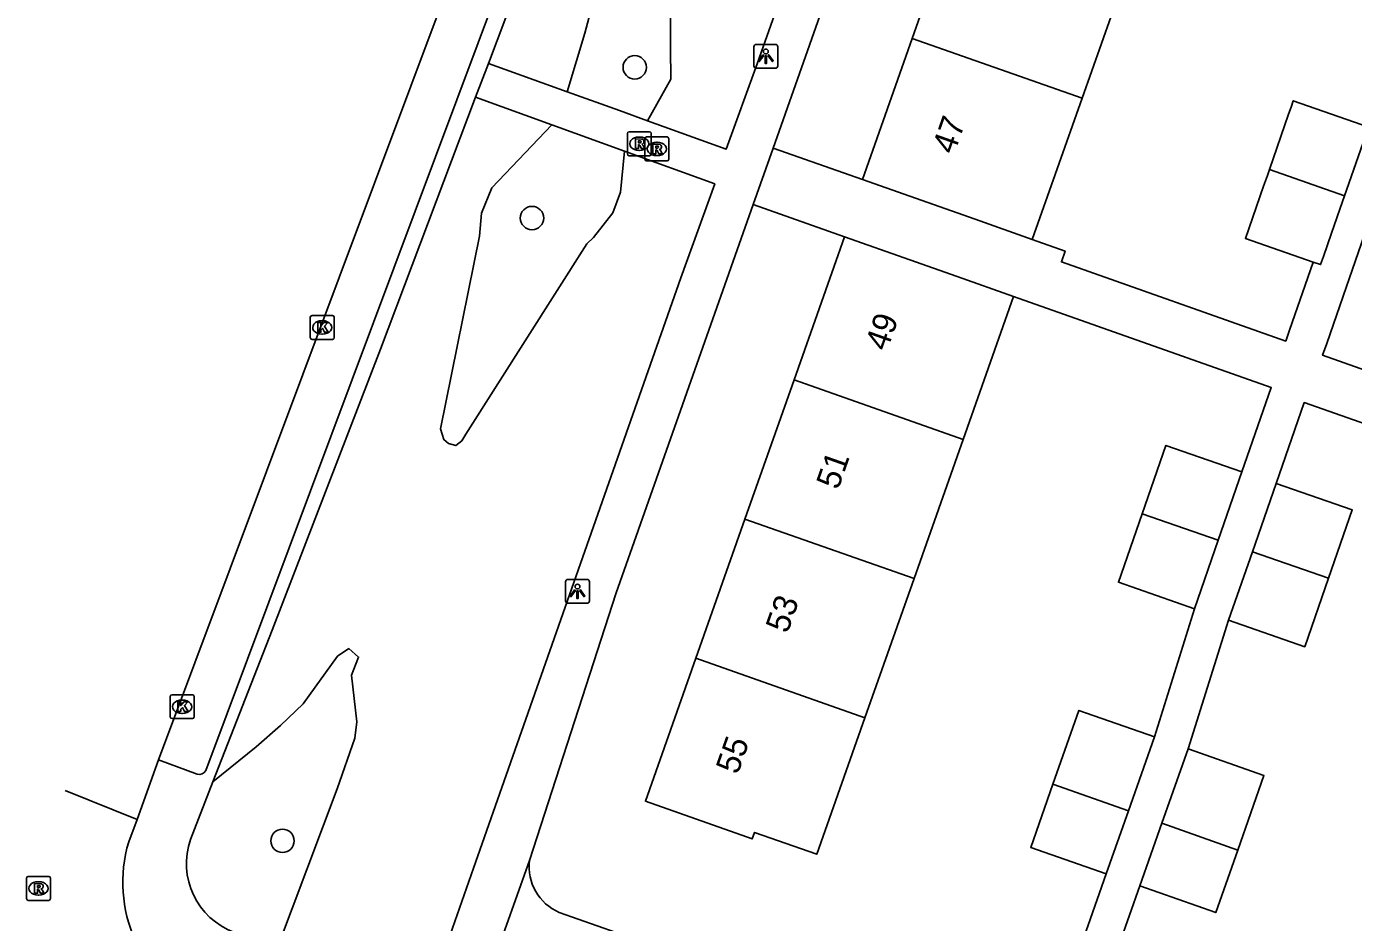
# Model space of a CAD drawing. Extents: x 163268 to 164360, y 381529 to 382285.
# Drawn here: x 163695 to 163750.6, y 381885.6 to 381923.1 of the extents above; entities that cross this region are included whole.
import ezdxf

# ---------------------------------------------------------------- set-up
doc = ezdxf.new("R2010")
doc.units = 0
for name, color, linetype in [('IMGEO_Boom', 7, 'Continuous'), ('IMGEO_Groenvoorziening', 7, 'Continuous'), ('IMGEO_Kolk', 7, 'Continuous'), ('IMGEO_Lichtpunt', 7, 'Continuous'), ('IMGEO_Pand', 7, 'Continuous'), ('IMGEO_Pand_nummerreeks', 7, 'Continuous'), ('IMGEO_Rijbaan_lokaal_open', 7, 'Continuous'), ('IMGEO_Rioolput', 7, 'Continuous'), ('IMGEO_Voetpad_open', 7, 'Continuous')]:
    doc.layers.add(name, color=color, linetype=linetype)

msp = doc.modelspace()

# ---------------------------------------------------------------- linework, layer by layer
at = {"layer": 'IMGEO_Boom'}
for centre in [(163720.477, 381921.428), (163716.178, 381915.121), (163705.736, 381889.056)]:
    msp.add_circle(centre, 0.489, dxfattribs=at)
at = {"layer": 'IMGEO_Groenvoorziening'}
for points in [[(163721.009, 381919.193), (163721.993, 381920.936), (163721.972, 381922.226), (163721.972, 381924.662), (163722.944, 381927.485), (163722.638, 381928.208), (163722.11, 381928.987), (163721.665, 381929.598), (163721.554, 381930.433), (163721.693, 381930.683), (163722.027, 381931.35), (163722.527, 381933.158), (163722.416, 381933.964), (163722.075, 381934.429), (163720.785, 381934.47), (163720.171, 381933.938), (163719.659, 381932.422), (163719.331, 381930.907), (163718.942, 381929.249), (163719.249, 381927.693), (163719.188, 381926.444), (163718.881, 381924.703), (163718.389, 381922.861), (163717.645, 381920.405)], [(163717.015, 381919.02), (163714.499, 381916.391), (163714.069, 381915.326), (163713.987, 381914.363), (163712.349, 381906.295), (163712.488, 381905.85), (163712.683, 381905.683), (163712.989, 381905.599), (163713.239, 381905.794), (163713.406, 381906.072), (163718.48, 381914.04), (163718.758, 381914.302), (163719.556, 381915.346), (163719.884, 381916.206), (163720.049, 381917.918)], [(163705.53, 381884.589), (163708.029, 381891.227), (163708.766, 381893.356), (163708.844, 381894.037), (163708.627, 381895.991), (163708.924, 381896.746), (163708.513, 381897.1), (163708.033, 381896.78), (163706.596, 381894.789), (163705.654, 381893.889), (163704.63, 381892.988), (163702.826, 381891.528)]]:
    msp.add_lwpolyline(points, dxfattribs=at)
at = {"layer": 'IMGEO_Kolk'}
for p, q in [((163706.901, 381910.117), (163706.901, 381910.969)), ((163706.976, 381911.043), (163707.828, 381911.043)), ((163707.389, 381910.823), (163707.414, 381910.823)), ((163707.902, 381910.969), (163707.902, 381910.117)), ((163707.828, 381910.043), (163706.976, 381910.043)), ((163707.412, 381910.263), (163707.387, 381910.263)), ((163701.038, 381894.244), (163701.038, 381895.096)), ((163701.113, 381895.17), (163701.965, 381895.17)), ((163702.039, 381895.096), (163702.039, 381894.244)), ((163701.526, 381894.95), (163701.551, 381894.95)), ((163701.965, 381894.17), (163701.113, 381894.17)), ((163701.549, 381894.39), (163701.524, 381894.39))]:
    msp.add_line(p, q, dxfattribs=at)
for points in [[(163706.901, 381910.117), (163706.901, 381910.969)], [(163706.976, 381911.043), (163707.828, 381911.043)], [(163707.222, 381910.743), (163707.345, 381910.743), (163707.345, 381910.592), (163707.475, 381910.743), (163707.639, 381910.743), (163707.493, 381910.592), (163707.646, 381910.343), (163707.494, 381910.343), (163707.409, 381910.507), (163707.345, 381910.44), (163707.345, 381910.343), (163707.222, 381910.343), (163707.222, 381910.743)], [(163707.902, 381910.969), (163707.902, 381910.117)], [(163707.828, 381910.043), (163706.976, 381910.043)], [(163701.038, 381894.244), (163701.038, 381895.096)], [(163701.113, 381895.17), (163701.965, 381895.17)], [(163702.039, 381895.096), (163702.039, 381894.244)], [(163701.359, 381894.87), (163701.482, 381894.87), (163701.482, 381894.719), (163701.612, 381894.87), (163701.776, 381894.87), (163701.63, 381894.719), (163701.783, 381894.47), (163701.631, 381894.47), (163701.546, 381894.634), (163701.482, 381894.567), (163701.482, 381894.47), (163701.359, 381894.47), (163701.359, 381894.87)], [(163701.965, 381894.17), (163701.113, 381894.17)]]:
    msp.add_lwpolyline(points, dxfattribs=at)
for centre, start, end in [((163706.978, 381910.967), 91.552, 178.448), ((163706.978, 381910.967), 91.552, 178.448), ((163707.826, 381910.967), 1.552, 88.448), ((163707.826, 381910.967), 1.552, 88.448), ((163706.978, 381910.119), 181.552, 268.448), ((163706.978, 381910.119), 181.552, 268.448), ((163707.826, 381910.119), 271.552, 358.448), ((163707.826, 381910.119), 271.552, 358.448), ((163701.115, 381895.094), 91.552, 178.448), ((163701.115, 381895.094), 91.552, 178.448), ((163701.963, 381895.094), 1.552, 88.448), ((163701.963, 381895.094), 1.552, 88.448), ((163701.115, 381894.246), 181.552, 268.448), ((163701.115, 381894.246), 181.552, 268.448), ((163701.963, 381894.246), 271.552, 358.448), ((163701.963, 381894.246), 271.552, 358.448)]:
    msp.add_arc(centre, 0.0765, start, end, dxfattribs=at)
for centre, major_axis, ratio, start_param, end_param in [((163707.388, 381910.543), (-0.387, 0.002), 0.722429, 4.712389, 7.853982), ((163707.413, 381910.543), (-0.39, 0.002), 0.717154, 1.570796, 4.712389), ((163701.525, 381894.67), (-0.387, 0.002), 0.722429, 4.712389, 7.853982), ((163701.55, 381894.67), (-0.39, 0.002), 0.717154, 1.570796, 4.712389)]:
    msp.add_ellipse(centre, major_axis=major_axis, ratio=ratio, start_param=start_param, end_param=end_param, dxfattribs=at)
at = {"layer": 'IMGEO_Lichtpunt'}
for p, q in [((163725.465, 381922.293), (163725.465, 381921.486)), ((163725.465, 381922.293), (163725.465, 381921.486)), ((163726.367, 381922.388), (163725.559, 381922.388)), ((163726.367, 381922.388), (163725.559, 381922.388)), ((163726.461, 381921.486), (163726.461, 381922.293)), ((163726.461, 381921.486), (163726.461, 381922.293)), ((163725.559, 381921.392), (163726.367, 381921.392)), ((163725.559, 381921.392), (163726.367, 381921.392)), ((163718.486, 381899.996), (163717.678, 381899.996)), ((163718.486, 381899.996), (163717.678, 381899.996)), ((163717.584, 381899.901), (163717.584, 381899.094)), ((163717.584, 381899.901), (163717.584, 381899.094)), ((163718.58, 381899.094), (163718.58, 381899.901)), ((163718.58, 381899.094), (163718.58, 381899.901)), ((163717.678, 381899), (163718.486, 381899)), ((163717.678, 381899), (163718.486, 381899))]:
    msp.add_line(p, q, dxfattribs=at)
for points in [[(163725.839, 381921.957), (163725.878, 381921.929), (163725.69, 381921.667), (163725.652, 381921.694), (163725.839, 381921.957)], [(163725.941, 381921.909), (163725.988, 381921.909), (163725.988, 381921.587), (163725.941, 381921.587), (163725.941, 381921.909)], [(163726.051, 381921.929), (163726.089, 381921.956), (163726.276, 381921.694), (163726.237, 381921.666), (163726.051, 381921.929)], [(163717.958, 381899.565), (163717.997, 381899.537), (163717.809, 381899.275), (163717.771, 381899.302), (163717.958, 381899.565)], [(163718.06, 381899.517), (163718.107, 381899.517), (163718.107, 381899.195), (163718.06, 381899.195), (163718.06, 381899.517)], [(163718.17, 381899.537), (163718.208, 381899.564), (163718.395, 381899.302), (163718.356, 381899.274), (163718.17, 381899.537)]]:
    msp.add_lwpolyline(points, dxfattribs=at)
for centre in [(163725.964, 381922.091), (163718.083, 381899.699)]:
    msp.add_circle(centre, 0.0994, dxfattribs=at)
for centre, start, end in [((163725.559, 381922.293), 90, 180), ((163725.559, 381922.293), 90, 180), ((163726.367, 381922.293), 0, 90), ((163726.367, 381922.293), 0, 90), ((163725.559, 381921.486), 180, 270), ((163725.559, 381921.486), 180, 270), ((163726.367, 381921.486), 270, 0), ((163726.367, 381921.486), 270, 360), ((163717.678, 381899.901), 90, 180), ((163717.678, 381899.901), 90, 180), ((163718.486, 381899.901), 0, 90), ((163718.486, 381899.901), 0, 90), ((163717.678, 381899.094), 180, 270), ((163717.678, 381899.094), 180, 270), ((163718.486, 381899.094), 270, 0), ((163718.486, 381899.094), 270, 360)]:
    msp.add_arc(centre, 0.0946, start, end, dxfattribs=at)
at = {"layer": 'IMGEO_Pand'}
for points in [[(163734.114, 381928.385), (163732.089, 381922.641)], [(163739.201, 381920.133), (163741.226, 381925.877)], [(163732.089, 381922.641), (163730.005, 381916.731)], [(163732.089, 381922.641), (163739.201, 381920.133)], [(163737.117, 381914.223), (163739.201, 381920.133)], [(163747.037, 381917.147), (163747.844, 381919.47), (163747.947, 381919.767), (163748.037, 381920.027), (163750.874, 381919.042)], [(163750.181, 381916.054), (163751.039, 381918.522), (163751.182, 381918.935), (163750.874, 381919.042)], [(163730.005, 381916.731), (163734.721, 381915.068), (163737.117, 381914.223)], [(163748.874, 381913.28), (163746.036, 381914.266), (163746.795, 381916.452), (163746.952, 381916.903), (163747.037, 381917.147)], [(163750.181, 381916.054), (163747.037, 381917.147)], [(163748.874, 381913.28), (163749.181, 381913.174), (163749.298, 381913.512), (163749.639, 381914.493), (163750.097, 381915.811), (163750.181, 381916.054)], [(163729.255, 381914.333), (163727.144, 381908.347)], [(163736.329, 381911.838), (163733.971, 381912.67), (163729.255, 381914.333)], [(163734.218, 381905.852), (163736.329, 381911.838)], [(163727.144, 381908.347), (163725.091, 381902.525)], [(163727.144, 381908.347), (163734.218, 381905.852)], [(163732.166, 381900.03), (163734.218, 381905.852)], [(163745.891, 381904.502), (163742.707, 381905.607), (163741.712, 381902.743)], [(163744.896, 381901.637), (163745.891, 381904.502)], [(163747.321, 381904.016), (163746.327, 381901.152)], [(163749.511, 381900.046), (163750.505, 381902.91), (163747.321, 381904.016)], [(163725.091, 381902.525), (163723.038, 381896.701)], [(163732.166, 381900.03), (163725.091, 381902.525)], [(163741.712, 381902.743), (163740.718, 381899.879), (163743.902, 381898.773)], [(163744.896, 381901.637), (163741.712, 381902.743)], [(163743.902, 381898.773), (163744.896, 381901.637)], [(163746.327, 381901.152), (163745.332, 381898.288)], [(163749.511, 381900.046), (163746.327, 381901.152)], [(163730.112, 381894.207), (163732.166, 381900.03)], [(163745.332, 381898.288), (163748.516, 381897.182), (163749.511, 381900.046)], [(163723.038, 381896.701), (163720.927, 381890.714), (163725.397, 381889.138), (163725.493, 381889.412), (163728.098, 381888.494), (163729.761, 381893.21), (163730.112, 381894.207)], [(163723.038, 381896.701), (163730.112, 381894.207)], [(163742.227, 381893.406), (163739.067, 381894.518), (163737.981, 381891.433)], [(163741.14, 381890.319), (163742.227, 381893.406)], [(163743.633, 381892.911), (163742.536, 381889.794)], [(163745.714, 381888.672), (163746.812, 381891.792), (163743.633, 381892.911)], [(163737.981, 381891.433), (163737.048, 381888.783), (163740.208, 381887.671)], [(163737.981, 381891.433), (163741.14, 381890.319)], [(163740.208, 381887.671), (163741.14, 381890.319)], [(163742.536, 381889.794), (163741.614, 381887.176)], [(163745.714, 381888.672), (163742.536, 381889.794)], [(163741.614, 381887.176), (163744.793, 381886.057), (163745.714, 381888.672)]]:
    msp.add_lwpolyline(points, dxfattribs=at)
at = {"layer": 'IMGEO_Rijbaan_lokaal_open'}
for points in [[(163700.552, 381892.445), (163721.667, 381948.843)], [(163699.655, 381889.95), (163700.552, 381892.445)], [(163696.644, 381891.17), (163699.655, 381889.95)], [(163699.301, 381889.012), (163699.655, 381889.95)]]:
    msp.add_lwpolyline(points, dxfattribs=at)
msp.add_arc((163704.918, 381887.326), 5.865, 163.2915, 244.9732, dxfattribs=at)
at = {"layer": 'IMGEO_Rioolput'}
for p, q in [((163720.169, 381917.804), (163720.169, 381918.656)), ((163720.244, 381918.73), (163721.096, 381918.73)), ((163720.657, 381918.51), (163720.682, 381918.51)), ((163720.902, 381917.587), (163720.902, 381918.439)), ((163720.977, 381918.513), (163721.829, 381918.513)), ((163721.17, 381918.656), (163721.17, 381917.804)), ((163721.903, 381918.439), (163721.903, 381917.587)), ((163720.68, 381917.95), (163720.655, 381917.95)), ((163721.39, 381918.293), (163721.415, 381918.293)), ((163721.096, 381917.73), (163720.244, 381917.73)), ((163721.829, 381917.513), (163720.977, 381917.513)), ((163721.413, 381917.733), (163721.388, 381917.733)), ((163695.025, 381886.64), (163695.025, 381887.492)), ((163695.1, 381887.566), (163695.952, 381887.566)), ((163695.513, 381887.346), (163695.538, 381887.346)), ((163696.026, 381887.492), (163696.026, 381886.64)), ((163695.536, 381886.786), (163695.511, 381886.786)), ((163695.952, 381886.566), (163695.1, 381886.566))]:
    msp.add_line(p, q, dxfattribs=at)
for points in [[(163720.169, 381917.804), (163720.169, 381918.656)], [(163720.244, 381918.73), (163721.096, 381918.73)], [(163720.758, 381918.428), (163720.506, 381918.43), (163720.506, 381918.03)], [(163720.684, 381918.349), (163720.63, 381918.349), (163720.63, 381918.268)], [(163720.902, 381917.587), (163720.902, 381918.439)], [(163720.977, 381918.513), (163721.829, 381918.513)], [(163721.17, 381918.656), (163721.17, 381917.804)], [(163721.903, 381918.439), (163721.903, 381917.587)], [(163720.506, 381918.03), (163720.63, 381918.03), (163720.63, 381918.192), (163720.641, 381918.192)], [(163720.63, 381918.268), (163720.682, 381918.268)], [(163720.688, 381918.163), (163720.759, 381918.03), (163720.899, 381918.03), (163720.834, 381918.156)], [(163721.491, 381918.211), (163721.239, 381918.213), (163721.239, 381917.813)], [(163721.239, 381917.813), (163721.363, 381917.813), (163721.363, 381917.975), (163721.374, 381917.975)], [(163721.417, 381918.132), (163721.363, 381918.132), (163721.363, 381918.051)], [(163721.363, 381918.051), (163721.415, 381918.051)], [(163721.421, 381917.946), (163721.492, 381917.813), (163721.632, 381917.813), (163721.567, 381917.939)], [(163721.096, 381917.73), (163720.244, 381917.73)], [(163721.829, 381917.513), (163720.977, 381917.513)], [(163695.025, 381886.64), (163695.025, 381887.492)], [(163695.1, 381887.566), (163695.952, 381887.566)], [(163695.614, 381887.264), (163695.362, 381887.266), (163695.362, 381886.866)], [(163696.026, 381887.492), (163696.026, 381886.64)], [(163695.362, 381886.866), (163695.486, 381886.866), (163695.486, 381887.028), (163695.497, 381887.028)], [(163695.54, 381887.185), (163695.486, 381887.185), (163695.486, 381887.104)], [(163695.486, 381887.104), (163695.538, 381887.104)], [(163695.544, 381886.999), (163695.615, 381886.866), (163695.755, 381886.866), (163695.69, 381886.992)], [(163695.952, 381886.566), (163695.1, 381886.566)]]:
    msp.add_lwpolyline(points, dxfattribs=at)
for centre, radius, start, end in [((163720.246, 381918.654), 0.0765, 91.552, 178.448), ((163720.246, 381918.654), 0.0765, 91.552, 178.448), ((163720.69, 381918.253), 0.0964, 77.0061, 93.1865), ((163720.704, 381918.31), 0.0378, 276.6634, 79.6772), ((163720.757, 381918.318), 0.109, 350.3612, 89.416), ((163720.979, 381918.437), 0.0765, 91.552, 178.448), ((163720.979, 381918.437), 0.0765, 91.552, 178.448), ((163721.094, 381918.654), 0.0765, 1.552, 88.448), ((163721.094, 381918.654), 0.0765, 1.552, 88.448), ((163721.827, 381918.437), 0.0765, 1.552, 88.448), ((163721.827, 381918.437), 0.0765, 1.552, 88.448), ((163720.246, 381917.806), 0.0765, 181.552, 268.448), ((163720.246, 381917.806), 0.0765, 181.552, 268.448), ((163720.64, 381918.139), 0.0533, 26.0293, 88.6989), ((163720.666, 381918.457), 0.19, 274.7715, 282.9687), ((163720.755, 381918.318), 0.112, 277.5842, 350.9817), ((163720.739, 381918.103), 0.108, 29.5134, 73.7905), ((163721.094, 381917.806), 0.0765, 271.552, 358.448), ((163721.094, 381917.806), 0.0765, 271.552, 358.448), ((163721.373, 381917.922), 0.0533, 26.0293, 88.6989), ((163721.399, 381918.24), 0.19, 274.7715, 282.9687), ((163721.423, 381918.036), 0.0964, 77.0061, 93.1865), ((163721.437, 381918.093), 0.0378, 276.6634, 79.6772), ((163721.49, 381918.101), 0.109, 350.3612, 89.416), ((163721.488, 381918.101), 0.112, 277.5842, 350.9817), ((163721.472, 381917.886), 0.108, 29.5134, 73.7905), ((163720.979, 381917.589), 0.0765, 181.552, 268.448), ((163720.979, 381917.589), 0.0765, 181.552, 268.448), ((163721.827, 381917.589), 0.0765, 271.552, 358.448), ((163721.827, 381917.589), 0.0765, 271.552, 358.448), ((163695.102, 381887.49), 0.0765, 91.552, 178.448), ((163695.102, 381887.49), 0.0765, 91.552, 178.448), ((163695.613, 381887.154), 0.109, 350.3612, 89.416), ((163695.95, 381887.49), 0.0765, 1.552, 88.448), ((163695.95, 381887.49), 0.0765, 1.552, 88.448), ((163695.496, 381886.975), 0.0533, 26.0293, 88.6989), ((163695.522, 381887.293), 0.19, 274.7715, 282.9687), ((163695.546, 381887.089), 0.0964, 77.0061, 93.1865), ((163695.56, 381887.146), 0.0378, 276.6634, 79.6772), ((163695.611, 381887.154), 0.112, 277.5842, 350.9817), ((163695.595, 381886.939), 0.108, 29.5134, 73.7905), ((163695.102, 381886.642), 0.0765, 181.552, 268.448), ((163695.102, 381886.642), 0.0765, 181.552, 268.448), ((163695.95, 381886.642), 0.0765, 271.552, 358.448), ((163695.95, 381886.642), 0.0765, 271.552, 358.448)]:
    msp.add_arc(centre, radius, start, end, dxfattribs=at)
for centre, major_axis, ratio, start_param, end_param in [((163720.656, 381918.23), (-0.387, 0.002), 0.722429, 4.712389, 7.853982), ((163720.681, 381918.23), (-0.39, 0.002), 0.717154, 1.570796, 4.712389), ((163721.389, 381918.013), (-0.387, 0.002), 0.722429, 4.712389, 7.853982), ((163721.414, 381918.013), (-0.39, 0.002), 0.717154, 1.570796, 4.712389), ((163695.512, 381887.066), (-0.387, 0.002), 0.722429, 4.712389, 7.853982), ((163695.537, 381887.066), (-0.39, 0.002), 0.717154, 1.570796, 4.712389)]:
    msp.add_ellipse(centre, major_axis=major_axis, ratio=ratio, start_param=start_param, end_param=end_param, dxfattribs=at)
at = {"layer": 'IMGEO_Voetpad_open'}
for points in [[(163726.266, 381918.05), (163746.635, 381975.818)], [(163724.781, 381949.832), (163720.041, 381936.884), (163716.491, 381927.268), (163714.364, 381921.587)], [(163721.009, 381919.193), (163724.309, 381918.005), (163725.595, 381921.578), (163733.407, 381943.696), (163734.382, 381946.498), (163729.871, 381948.065), (163724.781, 381949.832)], [(163702.531, 381891.996), (163723.538, 381948.149)], [(163758.439, 381935.741), (163756.351, 381929.753), (163755.357, 381926.889), (163754.362, 381924.025), (163752.254, 381917.979), (163751.26, 381915.114), (163750.265, 381912.25), (163749.438, 381909.87), (163749.265, 381909.379), (163757.42, 381906.499), (163760.627, 381905.919)], [(163713.821, 381920.179), (163714.364, 381921.587)], [(163714.364, 381921.587), (163717.645, 381920.405)], [(163713.821, 381920.179), (163709.833, 381909.63), (163705.3, 381897.879), (163702.826, 381891.528)], [(163717.015, 381919.02), (163713.821, 381920.179)], [(163717.645, 381920.405), (163719.838, 381919.615), (163721.009, 381919.193)], [(163720.049, 381917.918), (163717.015, 381919.02)], [(163712.46, 381884.291), (163713.726, 381887.91), (163722.406, 381912.623), (163723.829, 381916.546), (163720.049, 381917.918)], [(163725.431, 381915.681), (163726.266, 381918.05)], [(163730.005, 381916.731), (163726.266, 381918.05)], [(163716.074, 381888.233), (163719.701, 381899.432), (163725.431, 381915.681)], [(163725.431, 381915.681), (163729.255, 381914.333)], [(163737.117, 381914.223), (163738.49, 381913.739), (163738.331, 381913.286), (163747.723, 381909.973), (163747.883, 381910.426), (163748.874, 381913.28)], [(163736.329, 381911.838), (163747.117, 381908.032), (163745.891, 381904.502)], [(163747.321, 381904.016), (163748.494, 381907.396), (163759.885, 381903.401)], [(163743.902, 381898.773), (163742.227, 381893.406)], [(163743.633, 381892.911), (163745.332, 381898.288)], [(163700.552, 381892.445), (163702.171, 381891.843)], [(163702.826, 381891.528), (163701.887, 381889.118)], [(163716.074, 381888.233), (163714.008, 381882.427)], [(163740.208, 381887.671), (163737.187, 381879.077)], [(163738.593, 381878.583), (163741.614, 381887.176)], [(163737.187, 381879.077), (163717.319, 381886.062)]]:
    msp.add_lwpolyline(points, dxfattribs=at)
for centre, radius, start, end in [((163702.243, 381892.173), 0.338, 257.6848, 328.3662), ((163704.79, 381888.108), 3.073, 160.8129, 249.7706), ((163718.135, 381887.973), 2.078, 172.8029, 246.8629)]:
    msp.add_arc(centre, radius, start, end, dxfattribs=at)

# ---------------------------------------------------------------- texts
at = {"layer": 'IMGEO_Pand_nummerreeks'}
for s, rotation, p in [('47', 70.5777, (163733.842, 381917.749)), ('49', 70.5775, (163731.033, 381909.51)), ('51', 70.5775, (163728.988, 381903.713)), ('53', 70.5775, (163726.869, 381897.701)), ('55', 70.5775, (163724.787, 381891.796))]:
    msp.add_text(s, height=1, rotation=rotation, dxfattribs=at).set_placement(p)

doc.saveas('drawing.dxf')
